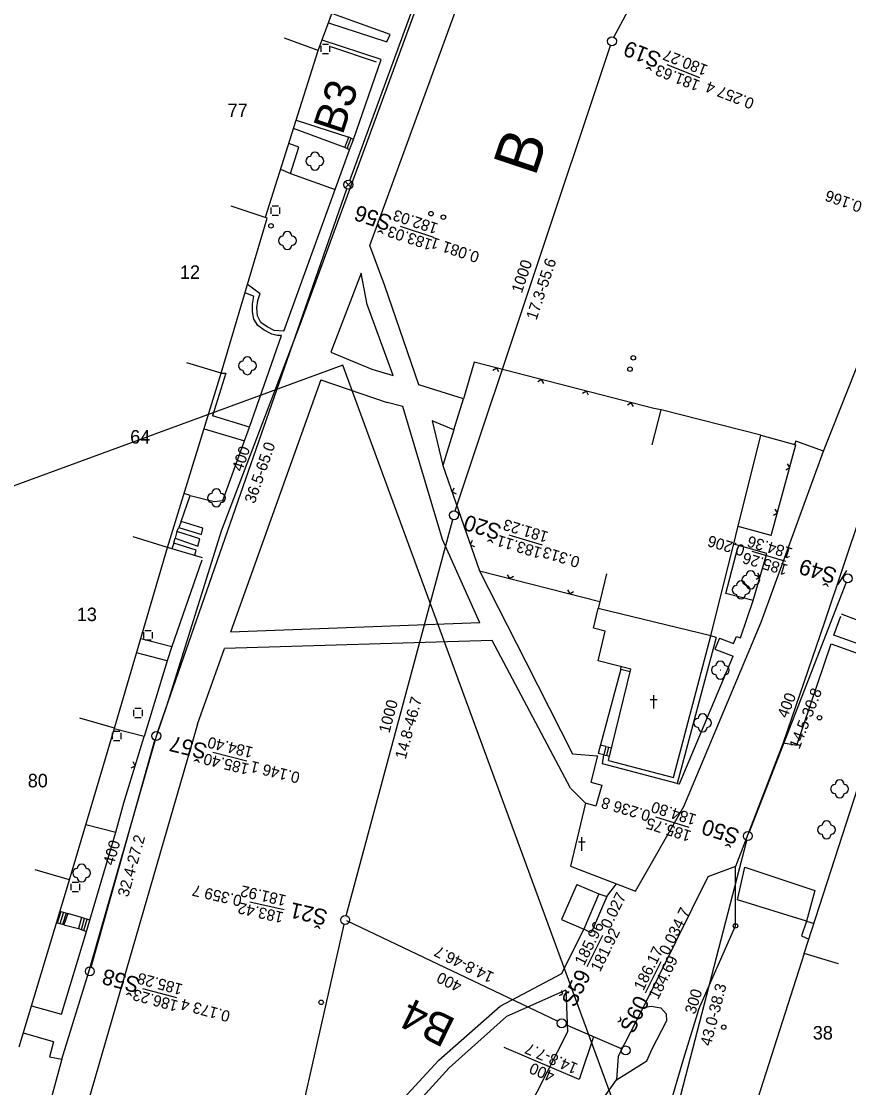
# Model space of a CAD drawing. Extents: x -574526 to -573537, y -1188297 to -1187280.
# Drawn here: x -573970.1 to -573878, y -1187881.2 to -1187762.5 of the extents above; entities that cross this region are included whole.
import ezdxf

# ---------------------------------------------------------------- set-up
doc = ezdxf.new("R2010")
doc.units = 0
for name, color, linetype in [('Vrstva 12', 7, 'Continuous'), ('Vrstva 13', 7, 'Continuous'), ('Vrstva 14', 7, 'Continuous'), ('Vrstva 17', 7, 'Continuous'), ('Vrstva 18', 7, 'Continuous'), ('Vrstva 2', 7, 'Continuous'), ('Vrstva 21', 7, 'Continuous'), ('Vrstva 4', 7, 'Continuous'), ('Vrstva 5', 7, 'Continuous'), ('Vrstva 6', 7, 'Continuous'), ('Vrstva 63', 7, 'Continuous'), ('Vrstva 7', 7, 'Continuous'), ('Vrstva 8', 7, 'Continuous'), ('Vrstva 9', 7, 'Continuous')]:
    doc.layers.add(name, color=color, linetype=linetype)

# ---------------------------------------------------------------- blocks, each defined once
blk = doc.blocks.new('4$091')
at = {"layer": 'Vrstva 5'}
for p, q in [((-0.75, 0), (0.75, 0)), ((0, -2), (0, 1))]:
    blk.add_line(p, q, dxfattribs=at)
blk = doc.blocks.new('3$130')
at = {"layer": 'Vrstva 8'}
blk.add_circle((0, 0), 0.001, dxfattribs=at)
for centre, start, end in [((-1, 0), 90, 270), ((0, 1), 0, 180), ((1, 0), 270, 90), ((0, -1), 180, 0)]:
    blk.add_arc(centre, 1, start, end, dxfattribs=at)
blk = doc.blocks.new('6$010')
at = {"layer": 'Vrstva 21'}
blk.add_circle((0, 0), 0.5, dxfattribs=at)
blk = doc.blocks.new('6$091')
at = {"layer": 'Vrstva 21'}
for p, q in [((-1, 0.7), (-1, -0.7)), ((0.7, 1), (-0.7, 1)), ((1, -0.7), (1, 0.7)), ((-0.7, -1), (0.7, -1))]:
    blk.add_line(p, q, dxfattribs=at)
blk = doc.blocks.new('200')
at = {"layer": 'Vrstva 63'}
blk.add_lwpolyline([(0, 0), (210, 0), (210, 297), (0, 297), (0, 0)], close=True, dxfattribs=at)

msp = doc.modelspace()

# ---------------------------------------------------------------- linework, layer by layer
at = {"layer": 'Vrstva 13'}
for p, q in [((-573894.62, -1187768.77), (-573898.25, -1187767.34)), ((-573927.95, -1187785.31), (-573924.24, -1187786.53)), ((-573912.1, -1187820.83), (-573915.84, -1187819.7)), ((-573885.04, -1187822.62), (-573888.79, -1187821.52)), ((-573948.8, -1187843.88), (-573945.01, -1187844.81)), ((-573895.79, -1187852.26), (-573899.51, -1187851.09)), ((-573944.68, -1187860.53), (-573940.87, -1187861.4)), ((-573905.45, -1187864.26), (-573907.18, -1187867.76)), ((-573898.94, -1187867.21), (-573900.67, -1187870.71)), ((-573956.64, -1187870.17), (-573952.87, -1187871.19))]:
    msp.add_line(p, q, dxfattribs=at)
msp.add_lwpolyline([(-573906.43, -1187875.56), (-573908.02, -1187880.32), (-573916.37, -1187876.76)], dxfattribs=at)
at = {"layer": 'Vrstva 17'}
for p, q in [((-573934.08, -1187781.02), (-573933.37, -1187780.31)), ((-573934.08, -1187780.31), (-573933.37, -1187781.02))]:
    msp.add_line(p, q, dxfattribs=at)
at = {"layer": 'Vrstva 2'}
for p, q in [((-573933.56, -1187780.2), (-573915.63, -1187731.25)), ((-573904.16, -1187764.26), (-573887.77, -1187733.18)), ((-573921.82, -1187817), (-573904.55, -1187765.18)), ((-573954.95, -1187841.57), (-573933.89, -1187781.14)), ((-573933.95, -1187862.07), (-573922.1, -1187817.96)), ((-573889.08, -1187852.74), (-573878.31, -1187824.99)), ((-573962.36, -1187867.79), (-573955.25, -1187842.53)), ((-573898.72, -1187889.85), (-573889.38, -1187853.69)), ((-573946.46, -1187917.23), (-573934.19, -1187863.04)), ((-573910.44, -1187873.83), (-573933.88, -1187862.65)), ((-573903.33, -1187876.88), (-573909.53, -1187874.24))]:
    msp.add_line(p, q, dxfattribs=at)
at = {"layer": 'Vrstva 4'}
msp.add_line((-573935.71, -1187765.29), (-573930.62, -1187767.01), dxfattribs=at)
at = {"layer": 'Vrstva 6'}
for p, q in [((-573934.1, -1187776.55), (-573933.67, -1187775.4)), ((-573933.86, -1187776.66), (-573933.43, -1187775.51)), ((-573933.16, -1187775.63), (-573933.67, -1187775.4)), ((-573933.59, -1187776.78), (-573934.1, -1187776.55)), ((-573933.59, -1187776.78), (-573933.16, -1187775.63)), ((-573919.71, -1187800.45), (-573920.89, -1187804.51)), ((-573899.74, -1187805.6), (-573919.71, -1187800.45)), ((-573921.99, -1187807.99), (-573920.89, -1187804.51)), ((-573898.91, -1187805.76), (-573899.74, -1187805.6)), ((-573921.99, -1187807.99), (-573923.2, -1187811.96)), ((-573887.81, -1187808.58), (-573883.9, -1187809.64)), ((-573886.66, -1187819.74), (-573883.9, -1187809.64)), ((-573923.2, -1187811.96), (-573919.13, -1187823.69)), ((-573886.66, -1187819.74), (-573890.33, -1187818.74)), ((-573949.95, -1187822.24), (-573953.85, -1187821.07)), ((-573887.16, -1187821.73), (-573890.82, -1187820.7)), ((-573888.66, -1187826.98), (-573887.16, -1187821.73)), ((-573919.13, -1187823.69), (-573905.73, -1187827.07)), ((-573871.48, -1187831.31), (-573878.83, -1187828.51)), ((-573903.41, -1187834.62), (-573903.34, -1187834.35)), ((-573903.41, -1187834.62), (-573902.35, -1187834.89)), ((-573956.47, -1187842.12), (-573959.78, -1187841.28)), ((-573958.45, -1187848.65), (-573956.47, -1187842.12)), ((-573905.05, -1187843.23), (-573905.29, -1187844.15)), ((-573905.05, -1187843.23), (-573904.41, -1187843.38)), ((-573905.29, -1187844.15), (-573904.64, -1187844.3)), ((-573904.76, -1187843.3), (-573905, -1187844.22)), ((-573904.47, -1187843.37), (-573904.71, -1187844.29)), ((-573958.7, -1187849.51), (-573958.45, -1187848.65)), ((-573959.6, -1187852.76), (-573958.7, -1187849.51)), ((-573962.93, -1187851.91), (-573959.6, -1187852.76)), ((-573965.71, -1187861.61), (-573966.14, -1187862.92)), ((-573965.42, -1187861.69), (-573965.84, -1187862.99)), ((-573965.71, -1187861.61), (-573964.96, -1187861.83)), ((-573965.13, -1187861.78), (-573965.55, -1187863.06)), ((-573964.96, -1187861.83), (-573965.38, -1187863.1)), ((-573965.38, -1187863.1), (-573966.14, -1187862.92)), ((-573963.42, -1187862.27), (-573963.77, -1187863.48)), ((-573963.43, -1187863.61), (-573963.08, -1187862.38)), ((-573962.51, -1187862.56), (-573963.42, -1187862.27)), ((-573963.15, -1187863.72), (-573962.79, -1187862.47)), ((-573962.87, -1187863.83), (-573962.51, -1187862.56)), ((-573963.77, -1187863.48), (-573962.87, -1187863.83))]:
    msp.add_line(p, q, dxfattribs=at)
for points in [[(-573916.96, -1187801.52), (-573917.21, -1187801.09), (-573917.64, -1187801.35)], [(-573911.97, -1187802.81), (-573912.22, -1187802.38), (-573912.65, -1187802.63)], [(-573906.98, -1187804.1), (-573907.23, -1187803.67), (-573907.66, -1187803.92)], [(-573901.98, -1187805.38), (-573902.24, -1187804.96), (-573902.66, -1187805.21)], [(-573885.02, -1187812.41), (-573884.59, -1187812.17), (-573884.84, -1187811.74)], [(-573921.97, -1187814.45), (-573922.18, -1187814.89), (-573921.74, -1187815.11)], [(-573886.4, -1187817.46), (-573885.97, -1187817.22), (-573886.22, -1187816.79)], [(-573919.93, -1187820.31), (-573920.15, -1187820.76), (-573919.7, -1187820.97)], [(-573916.03, -1187824.11), (-573915.78, -1187824.53), (-573915.36, -1187824.28)], [(-573888.34, -1187824.6), (-573887.91, -1187824.35), (-573888.15, -1187823.92)], [(-573909.33, -1187825.8), (-573909.08, -1187826.23), (-573908.66, -1187825.97)], [(-573957.9, -1187845.62), (-573957.46, -1187845.39), (-573957.69, -1187844.95)]]:
    msp.add_lwpolyline(points, dxfattribs=at)
at = {"layer": 'Vrstva 7'}
for p, q in [((-573937.08, -1187765.74), (-573930.56, -1187748.09)), ((-573937.08, -1187765.74), (-573940.83, -1187764.35)), ((-573942.95, -1187784.29), (-573937.08, -1187765.74)), ((-573942.78, -1187784.39), (-573946.76, -1187783.08)), ((-573947.87, -1187801.66), (-573942.78, -1187784.39)), ((-573953.85, -1187821.07), (-573947.87, -1187801.66)), ((-573947.87, -1187801.66), (-573951.71, -1187800.53)), ((-573899.89, -1187809.64), (-573898.91, -1187805.76)), ((-573887.81, -1187808.58), (-573898.91, -1187805.76)), ((-573953.85, -1187821.07), (-573957.67, -1187819.89)), ((-573959.76, -1187841.2), (-573953.85, -1187821.07)), ((-573904.99, -1187823.99), (-573905.93, -1187827.88)), ((-573906.44, -1187830.06), (-573905.93, -1187827.88)), ((-573893.36, -1187830.92), (-573905.93, -1187827.88)), ((-573905.13, -1187830.4), (-573906.44, -1187830.06)), ((-573905.91, -1187833.69), (-573905.13, -1187830.4)), ((-573902.28, -1187834.62), (-573905.91, -1187833.69)), ((-573904.76, -1187844.8), (-573902.28, -1187834.62)), ((-573959.76, -1187841.2), (-573963.6, -1187840.07)), ((-573964.76, -1187858.09), (-573959.76, -1187841.2)), ((-573904.76, -1187844.8), (-573897.52, -1187846.7)), ((-573882.98, -1187866.29), (-573876.16, -1187845.2)), ((-573964.76, -1187858.09), (-573968.59, -1187856.95)), ((-573970.35, -1187876.67), (-573964.76, -1187858.09)), ((-573908.29, -1187858.58), (-573909.99, -1187862.5)), ((-573908.29, -1187858.58), (-573905.83, -1187859.64)), ((-573905.83, -1187859.64), (-573907.53, -1187863.56)), ((-573909.99, -1187862.5), (-573907.53, -1187863.56)), ((-573882.98, -1187866.29), (-573888.16, -1187882.4)), ((-573879.15, -1187867.45), (-573882.98, -1187866.29))]:
    msp.add_line(p, q, dxfattribs=at)
msp.add_lwpolyline([(-573897.52, -1187846.7), (-573893.36, -1187830.92), (-573887.81, -1187808.58)], dxfattribs=at)
at = {"layer": 'Vrstva 8'}
for centre in [(-573904.39, -1187764.71), (-573933.73, -1187780.67), (-573921.97, -1187817.48), (-573878.13, -1187824.52), (-573955.11, -1187842.05), (-573889.26, -1187853.2), (-573934.08, -1187862.55), (-573962.5, -1187868.27), (-573909.99, -1187874.05), (-573902.86, -1187877.08)]:
    msp.add_circle(centre, 0.5, dxfattribs=at)
at = {"layer": 'Vrstva 9'}
for p, q in [((-573939.1, -1187796.23), (-573911.45, -1187720.81)), ((-573931.35, -1187787.44), (-573908.51, -1187724.91)), ((-573929.06, -1187763.94), (-573935.55, -1187761.61)), ((-573935.95, -1187762.67), (-573929.44, -1187764.78)), ((-573930.07, -1187766.74), (-573936.65, -1187764.57)), ((-573929.44, -1187764.78), (-573929.06, -1187763.94)), ((-573933.16, -1187775.63), (-573930.07, -1187766.74)), ((-573939.53, -1187773.5), (-573933.67, -1187775.4)), ((-573934.1, -1187776.55), (-573939.83, -1187774.43)), ((-573939.23, -1187776.5), (-573940.35, -1187776.09)), ((-573940.18, -1187779.42), (-573939.23, -1187776.5)), ((-573940.92, -1187796.97), (-573933.59, -1187776.78)), ((-573941.26, -1187778.95), (-573940.18, -1187779.42)), ((-573940.18, -1187779.42), (-573935.19, -1187781.2)), ((-573880.84, -1187810.33), (-573870.98, -1187785.45)), ((-573929.68, -1187791.94), (-573931.35, -1187787.44)), ((-573932.3, -1187790.53), (-573935.66, -1187799.34)), ((-573931.64, -1187794), (-573932.3, -1187790.53)), ((-573944.95, -1187791.77), (-573943.54, -1187792.81)), ((-573925.89, -1187802.98), (-573929.68, -1187791.94)), ((-573945.23, -1187792.69), (-573944.23, -1187793.08)), ((-573928.73, -1187801.92), (-573931.64, -1187794)), ((-573947.85, -1187819.23), (-573939.1, -1187796.23)), ((-573944.74, -1187807.68), (-573941.17, -1187797.47)), ((-573935.66, -1187799.34), (-573931.1, -1187801.23)), ((-573947.38, -1187801.66), (-573948.86, -1187806.42)), ((-573947.87, -1187801.66), (-573947.38, -1187801.66)), ((-573931.1, -1187801.23), (-573928.73, -1187801.92)), ((-573936.77, -1187802.4), (-573946.84, -1187830.5)), ((-573936.77, -1187802.4), (-573929.4, -1187804.92)), ((-573920.89, -1187804.51), (-573925.89, -1187802.98)), ((-573927.66, -1187805.37), (-573929.4, -1187804.92)), ((-573944.74, -1187807.68), (-573948.86, -1187806.42)), ((-573923.25, -1187820.2), (-573927.66, -1187805.37)), ((-573921.99, -1187807.99), (-573924.41, -1187806.97)), ((-573924.41, -1187806.97), (-573923.2, -1187811.96)), ((-573949.78, -1187807.85), (-573945.3, -1187809.2)), ((-573945.3, -1187809.2), (-573944.74, -1187807.68)), ((-573947.7, -1187815.85), (-573945.3, -1187809.2)), ((-573883.9, -1187809.24), (-573884.06, -1187809.6)), ((-573880.84, -1187810.33), (-573883.9, -1187809.24)), ((-573887.77, -1187829.4), (-573880.84, -1187810.33)), ((-573952.35, -1187818.17), (-573951.33, -1187815.28)), ((-573951.33, -1187815.28), (-573951.99, -1187815.05)), ((-573951.33, -1187815.28), (-573948.66, -1187815.95)), ((-573948.66, -1187815.95), (-573947.7, -1187815.85)), ((-573876.59, -1187817.11), (-573880.72, -1187829.39)), ((-573952.35, -1187818.17), (-573952.6, -1187818.84)), ((-573949.91, -1187818.93), (-573952.35, -1187818.17)), ((-573953.88, -1187838.59), (-573947.85, -1187819.23)), ((-573952.83, -1187819.3), (-573953, -1187820.05)), ((-573952.83, -1187819.3), (-573952.6, -1187818.84)), ((-573950.24, -1187820.12), (-573952.83, -1187819.3)), ((-573952.6, -1187818.84), (-573950.07, -1187819.62)), ((-573950.07, -1187819.62), (-573949.91, -1187818.93)), ((-573953.15, -1187820.59), (-573953.37, -1187821.21)), ((-573953.15, -1187820.59), (-573953, -1187820.05)), ((-573950.67, -1187821.38), (-573953.15, -1187820.59)), ((-573953, -1187820.05), (-573950.49, -1187820.91)), ((-573950.49, -1187820.91), (-573950.24, -1187820.12)), ((-573919.08, -1187829.47), (-573923.25, -1187820.2)), ((-573950.82, -1187821.91), (-573950.67, -1187821.38)), ((-573891.71, -1187826.18), (-573890.36, -1187821.09)), ((-573950.03, -1187822.5), (-573953.38, -1187832.08)), ((-573919.13, -1187823.69), (-573913.96, -1187833.82)), ((-573879.21, -1187825.21), (-573878.24, -1187823.62)), ((-573888.66, -1187826.98), (-573891.71, -1187826.18)), ((-573890.07, -1187831.15), (-573888.66, -1187826.98)), ((-573879.67, -1187830.82), (-573878.91, -1187828.72)), ((-573919.08, -1187829.47), (-573946.84, -1187830.5)), ((-573896.4, -1187849.93), (-573887.77, -1187829.4)), ((-573880.72, -1187829.39), (-573885.33, -1187842.83)), ((-573956.82, -1187831.19), (-573953.38, -1187832.08)), ((-573892.8, -1187831.09), (-573897.11, -1187847.36)), ((-573892.8, -1187831.09), (-573893.36, -1187830.92)), ((-573892.42, -1187831.16), (-573892.92, -1187832.39)), ((-573892.42, -1187831.16), (-573890.85, -1187831.77)), ((-573890.85, -1187831.77), (-573890.53, -1187830.98)), ((-573890.53, -1187830.98), (-573890.07, -1187831.15)), ((-573873.36, -1187833.11), (-573879.67, -1187830.82)), ((-573953.38, -1187832.08), (-573953.91, -1187833.69)), ((-573950.52, -1187840.75), (-573947.5, -1187832.32)), ((-573917.71, -1187831.44), (-573947.5, -1187832.32)), ((-573909, -1187847.86), (-573917.71, -1187831.44)), ((-573892.92, -1187832.39), (-573890.91, -1187833.17)), ((-573883.81, -1187843.09), (-573880, -1187831.81)), ((-573880, -1187831.81), (-573873.67, -1187834.09)), ((-573953.91, -1187833.69), (-573957.29, -1187832.8)), ((-573953.91, -1187833.69), (-573956.47, -1187842.12)), ((-573896.88, -1187847.4), (-573890.91, -1187833.17)), ((-573913.96, -1187833.82), (-573908.77, -1187844.04)), ((-573903.41, -1187834.62), (-573905.93, -1187844)), ((-573955.08, -1187842.07), (-573953.88, -1187838.59)), ((-573950.52, -1187840.75), (-573965.21, -1187891.48)), ((-573962.62, -1187868.34), (-573955.08, -1187842.07)), ((-573905.05, -1187843.23), (-573905.68, -1187843.08)), ((-573885.33, -1187842.83), (-573890.62, -1187856.61)), ((-573885.33, -1187842.83), (-573883.81, -1187843.09)), ((-573908.77, -1187844.04), (-573906, -1187844.28)), ((-573906, -1187844.28), (-573906.73, -1187847.2)), ((-573905.29, -1187844.15), (-573905.93, -1187844)), ((-573905.42, -1187845.17), (-573905.29, -1187844.15)), ((-573897.11, -1187847.36), (-573905.42, -1187845.17)), ((-573907.31, -1187849.56), (-573909, -1187847.86)), ((-573906.73, -1187847.2), (-573905.52, -1187847.54)), ((-573905.52, -1187847.54), (-573906.18, -1187849.89)), ((-573897.11, -1187847.36), (-573896.88, -1187847.4)), ((-573907.31, -1187849.56), (-573908.99, -1187856.56)), ((-573906.18, -1187849.89), (-573907.31, -1187849.56)), ((-573901.75, -1187859.34), (-573896.4, -1187849.93)), ((-573962.51, -1187862.56), (-573959.6, -1187852.76)), ((-573908.99, -1187856.56), (-573903.86, -1187858.53)), ((-573890.62, -1187856.61), (-573893.73, -1187857.74)), ((-573890.64, -1187863.21), (-573890.62, -1187856.61)), ((-573890.42, -1187860.31), (-573889.6, -1187856.66)), ((-573889.6, -1187856.66), (-573881.81, -1187859.26)), ((-573904.95, -1187859.93), (-573903.86, -1187858.53)), ((-573903.86, -1187858.53), (-573901.75, -1187859.34)), ((-573893.73, -1187857.74), (-573900.9, -1187872.29)), ((-573905.83, -1187859.64), (-573904.95, -1187859.93)), ((-573881.81, -1187859.26), (-573882.74, -1187862.67)), ((-573904.95, -1187859.93), (-573906.69, -1187863.97)), ((-573882.74, -1187862.67), (-573890.42, -1187860.31)), ((-573963.42, -1187862.27), (-573964.96, -1187861.83)), ((-573965.38, -1187863.1), (-573963.77, -1187863.48)), ((-573894.75, -1187872.56), (-573890.64, -1187863.21)), ((-573882.74, -1187862.67), (-573883.3, -1187864.33)), ((-573882.74, -1187862.67), (-573881.89, -1187862.93)), ((-573965.67, -1187873.04), (-573962.87, -1187863.83)), ((-573909.96, -1187868.49), (-573907.53, -1187863.56)), ((-573906.69, -1187863.97), (-573907.53, -1187863.56)), ((-573883.3, -1187864.33), (-573882.46, -1187864.68)), ((-573965.63, -1187878.06), (-573962.62, -1187868.34)), ((-573916.81, -1187872.13), (-573909.96, -1187868.49)), ((-573909.52, -1187870.38), (-573916.13, -1187873.28)), ((-573909.52, -1187870.38), (-573909.33, -1187875.01)), ((-573968.98, -1187872.11), (-573965.67, -1187873.04)), ((-573923.66, -1187878.16), (-573916.81, -1187872.13)), ((-573900.9, -1187872.29), (-573903.68, -1187877.71)), ((-573894.75, -1187872.56), (-573896.42, -1187877.97)), ((-573916.13, -1187873.28), (-573922.5, -1187879)), ((-573899.9, -1187876.9), (-573898.3, -1187873.81)), ((-573966.56, -1187876.11), (-573969.9, -1187875.16)), ((-573909.33, -1187875.01), (-573917.66, -1187891.35)), ((-573966.56, -1187876.11), (-573967, -1187877.77)), ((-573900.5, -1187878.23), (-573899.9, -1187876.9)), ((-573965.63, -1187878.06), (-573970.53, -1187896.01)), ((-573967, -1187877.77), (-573965.63, -1187878.06)), ((-573939.7, -1187895.52), (-573923.66, -1187878.16)), ((-573903.68, -1187877.71), (-573903.88, -1187880.34)), ((-573903.88, -1187880.34), (-573900.5, -1187878.23)), ((-573896.42, -1187877.97), (-573901, -1187893.54)), ((-573922.5, -1187879), (-573937.63, -1187895.62)), ((-573914.84, -1187895.88), (-573903.88, -1187880.34))]:
    msp.add_line(p, q, dxfattribs=at)
for points in [[(-573943.81, -1187796.35), (-573944.23, -1187795.65), (-573944.41, -1187794.83), (-573944.41, -1187793.98), (-573944.23, -1187793.08)], [(-573943.45, -1187796.02), (-573943.84, -1187795.27), (-573943.91, -1187794.39), (-573943.79, -1187793.57), (-573943.54, -1187792.81)], [(-573941.17, -1187797.47), (-573941.66, -1187797.46), (-573942.26, -1187797.31), (-573943.08, -1187796.87), (-573943.81, -1187796.35)], [(-573940.92, -1187796.97), (-573941.97, -1187796.92), (-573942.77, -1187796.49), (-573943.45, -1187796.02)], [(-573900.9, -1187872.29), (-573900.03, -1187872.13), (-573898.93, -1187872.34)], [(-573898.93, -1187872.34), (-573898.35, -1187873), (-573898.3, -1187873.81)]]:
    msp.add_lwpolyline(points, dxfattribs=at)

# ---------------------------------------------------------------- block references
at = {"layer": 'Vrstva 21', "xscale": 0.5, "yscale": 0.5}
for name, p in [('6$091', (-573936.27, -1187765.55)), ('6$091', (-573941.85, -1187783.58)), ('6$010', (-573924.52, -1187783.91)), ('6$010', (-573942.34, -1187785.26)), ('6$010', (-573923.15, -1187784.3)), ('6$010', (-573902.01, -1187799.95)), ('6$010', (-573902.38, -1187801.21)), ('6$091', (-573956.01, -1187830.85)), ('6$091', (-573957.13, -1187839.5)), ('6$010', (-573881.28, -1187840.03)), ('6$091', (-573959.52, -1187842.05)), ('6$091', (-573964.13, -1187858.87)), ('6$010', (-573890.64, -1187863.21)), ('6$010', (-573936.75, -1187871.72)), ('6$010', (-573891.94, -1187874.48))]:
    msp.add_blockref(name, p, dxfattribs=at)
at = {"layer": 'Vrstva 4', "xscale": 0.5, "yscale": 0.5}
for p in [(-573937.45, -1187778.05), (-573940.51, -1187786.9), (-573944.96, -1187800.83), (-573948.41, -1187815.55), (-573888.94, -1187824.68), (-573890.01, -1187825.79), (-573892.32, -1187834.73), (-573894.29, -1187840.6), (-573879.04, -1187847.96), (-573880.5, -1187852.51), (-573963.41, -1187857.32)]:
    msp.add_blockref('3$130', p, dxfattribs=at)
at = {"layer": 'Vrstva 5', "xscale": 0.5, "yscale": 0.5}
for p in [(-573899.74, -1187838.01), (-573907.74, -1187853.84)]:
    msp.add_blockref('4$091', p, dxfattribs=at)
at = {"layer": 'Vrstva 63', "xscale": 2.9999999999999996, "rotation": 20.160475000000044}
msp.add_blockref('200', (-574423.39, -1188296.69), dxfattribs=at)

# ---------------------------------------------------------------- texts
at = {"layer": 'Vrstva 12'}
for s, p in [('77', (-573947.17, -1187773.15)), ('12', (-573952.47, -1187791.16)), ('64', (-573958.01, -1187809.5)), ('13', (-573963.95, -1187829.27)), ('80', (-573969.41, -1187847.78)), ('38', (-573882.03, -1187875.86))]:
    msp.add_text(s, height=1.5, dxfattribs=at).set_placement(p)
at = {"layer": 'Vrstva 13'}
for s, height, rotation, p in [('180.27', 1.249, 158.5324, (-573893.62, -1187767.43)), ('181.63', 1.249, 158.5324, (-573894.48, -1187769.14)), ('0.257 4', 1.249, 158.5324, (-573888.44, -1187771.16)), ('0.166', 1.25, 160.6756, (-573876.43, -1187782.63)), ('182.03', 1.25, 161.7311, (-573923.64, -1187785.03)), ('183.03', 1.25, 161.7311, (-573924.25, -1187786.84)), ('0.081 1', 1.25, 161.7311, (-573919.04, -1187788.23)), ('181.23', 1.25, 163.1442, (-573911.37, -1187819.37)), ('183.11', 1.25, 163.1442, (-573912.09, -1187821.15)), ('0.206', 1.25, 163.6359, (-573889.49, -1187820.88)), ('184.36', 1.25, 163.6359, (-573884.18, -1187821.19)), ('0.313', 1.25, 163.1442, (-573907.86, -1187822.17)), ('185.26', 1.25, 163.6359, (-573884.71, -1187823.03)), ('184.40', 1.25, 166.215, (-573944.24, -1187843.34)), ('185.40', 1.25, 166.215, (-573944.69, -1187845.19)), ('0.146 1', 1.25, 166.215, (-573939.03, -1187846.15)), ('0.236 8', 1.25, 163.6359, (-573900, -1187850.41)), ('184.80', 1.25, 162.6291, (-573894.89, -1187850.85)), ('185.75', 1.25, 162.6291, (-573895.46, -1187852.67)), ('0.359 7', 1.25, 167.1419, (-573945.49, -1187859.85)), ('181.92', 1.25, 167.1419, (-573940.57, -1187859.82)), ('0.027', 1.25, 63.7257, (-573904.6, -1187863.63)), ('183.42', 1.25, 167.1419, (-573940.86, -1187861.71)), ('0.034 7', 1.25, 63.7257, (-573898.09, -1187866.57)), ('185.96', 1.25, 63.7257, (-573907.49, -1187867.72)), ('181.92', 1.25, 63.7257, (-573905.71, -1187868.42)), ('186.17', 1.25, 63.7257, (-573900.9, -1187870.51)), ('184.69', 1.25, 63.7257, (-573899.26, -1187871.5)), ('185.28', 1.25, 164.8989, (-573952.07, -1187869.73)), ('186.23', 1.25, 164.8989, (-573952.58, -1187871.57)), ('0.173 4', 1.25, 164.8989, (-573946.79, -1187872.74))]:
    msp.add_text(s, height=height, rotation=rotation, dxfattribs=at).set_placement(p)
at = {"layer": 'Vrstva 14'}
for s, height, rotation, p in [('B3', 3.5, 71.5717, (-573934.38, -1187775.23)), ('B', 5, 71.5717, (-573912.94, -1187779.88)), ('1000', 1.25, 71.5717, (-573914.42, -1187792.83)), ('17.3-55.6', 1.25, 71.5717, (-573912.79, -1187795.83)), ('400', 1.249, 70.793, (-573945.55, -1187812.7)), ('36.5-65.0', 1.249, 70.793, (-573944.15, -1187816.27)), ('400', 1.25, 68.7959, (-573884.87, -1187840.16)), ('14.5-30.8', 1.25, 68.7959, (-573883.53, -1187843.62)), ('1000', 1.25, 74.9614, (-573929.16, -1187841.82)), ('14.8-46.7', 1.25, 74.9614, (-573927.35, -1187844.73)), ('400', 1.25, 74.2683, (-573959.85, -1187856.56)), ('32.4-27.2', 1.25, 74.2683, (-573958.24, -1187860.08)), ('14.8-46.7', 1.25, 153.8456, (-573917.41, -1187868.49)), ('400', 1.25, 153.8456, (-573920.97, -1187869.52)), ('300', 1.25, 73.1265, (-573895.12, -1187873.13)), ('43.0-38.3', 1.25, 75.5283, (-573893.38, -1187876.66)), ('B4', 3.5, 153.8456, (-573921.61, -1187873.67)), ('14.8-7.7', 1.25, 156.8858, (-573908.07, -1187878.61)), ('400', 1.25, 156.8858, (-573910.66, -1187879.49))]:
    msp.add_text(s, height=height, rotation=rotation, dxfattribs=at).set_placement(p)
at = {"layer": 'Vrstva 18'}
for s, height, rotation, p in [('Š19', 1.749, 158.5324, (-573898.75, -1187766.12)), ('Š56', 1.75, 161.7311, (-573928.72, -1187784.22)), ('Š20', 1.75, 163.1442, (-573916.55, -1187818.6)), ('Š49', 1.75, 163.6359, (-573879.22, -1187823.47)), ('Š57', 1.75, 166.215, (-573949.31, -1187843)), ('Š50', 1.75, 162.6291, (-573890.05, -1187852.52)), ('Š21', 1.75, 167.1419, (-573935.92, -1187861.49)), ('Š58', 1.75, 164.8989, (-573956.81, -1187869.03)), ('Š59', 1.75, 63.7257, (-573908.51, -1187872.38)), ('Š60', 1.75, 63.7257, (-573902, -1187875.32))]:
    msp.add_text(s, height=height, rotation=rotation, dxfattribs=at).set_placement(p)

doc.saveas('drawing.dxf')
